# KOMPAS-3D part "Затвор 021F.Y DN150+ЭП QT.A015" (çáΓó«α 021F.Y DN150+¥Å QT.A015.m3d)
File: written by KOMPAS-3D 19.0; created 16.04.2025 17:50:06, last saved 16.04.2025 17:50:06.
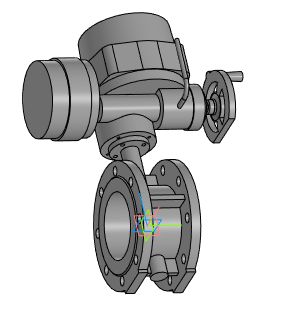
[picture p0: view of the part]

Document properties: Полное имя файла: Затвор 021F.Y DN150+ЭП QT.A015.a3d

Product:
- Part/product: Затвор 021F.Y DN150+ЭП QT.A015
    Масса: 113.131

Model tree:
1. Операция без истории:1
